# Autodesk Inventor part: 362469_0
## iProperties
Company: Mayer & Müller AG Schaltgeräte
Shininess: 64.0
Length Units: 11269
Angle Units: 11279
Time Units: 11290
Mass Units: 11283
Length Display Precision: 3
Angle Display Precision: 2
Compacted: True
Document SubType Name: Modeling
Created: 2006-10
Material: PU 1420 NAF
Manufacturer: Standard
Standards Organization: Custom
Description: Supraplast / Schwarz 9005
Density: 0.94 g/cm^3
Density: 0.0
Volumn: 0.0
Area: 0.0
PropertySet Name: Model Information
Control State: 0
Master: False
Checked Out: False
HalbzeugNorm: Typ 803
Author: T.Messerschmitt
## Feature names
1. Extrusion1
2. Extrusion2
3. Extrusion3
4. Extrusion6
5. Extrusion8
6. Extrusion9
7. Extrusion10
8. Extrusion11
9. Bohrung1 [Hole]
10. Extrusion12
11. Rundung1 [Fillet]
12. Rundung2 [Fillet]
13. Rundung3 [Fillet]
14. Extrusion13
15. Extrusion14
16. Rundung4 [Fillet]
17. Extrusion15
18. Rundung5 [Fillet]
19. Rundung6 [Fillet]
20. Bohrung2 [Hole]
21. Bohrung3 [Hole]
22. Bohrung4 [Hole]
23. Extrusion16
24. Bohrung5 [Hole]
25. Bohrung6 [Hole]
26. Bohrung7 [Hole]
27. Extrusion17
28. Extrusion18
29. Extrusion19
30. Extrusion20
31. Extrusion21
32. Extrusion22
33. Extrusion23
34. Extrusion24
35. Extrusion25
36. Rundung7 [Fillet]
37. Extrusion26
38. Rundung8 [Fillet]
39. Extrusion27
40. Extrusion28
41. Extrusion29
42. Extrusion31
43. Extrusion32
44. Extrusion33
45. Extrusion34
46. Extrusion35
47. Rundung9 [Fillet]
48. Rundung10 [Fillet]
49. Extrusion36
50. Extrusion37
51. Extrusion39
52. Fase1 [Chamfer]
53. Extrusion43
54. Rundung12 [Fillet]
55. Extrusion44
56. Bohrung10 [Hole]
57. Fase2 [Chamfer]
58. Fase3 [Chamfer]
59. Extrusion45
60. Extrusion46
61. Rundung13 [Fillet]
62. Rundung14 [Fillet]
63. Rundung15 [Fillet]
64. Rundung16 [Fillet]
65. Extrusion47
